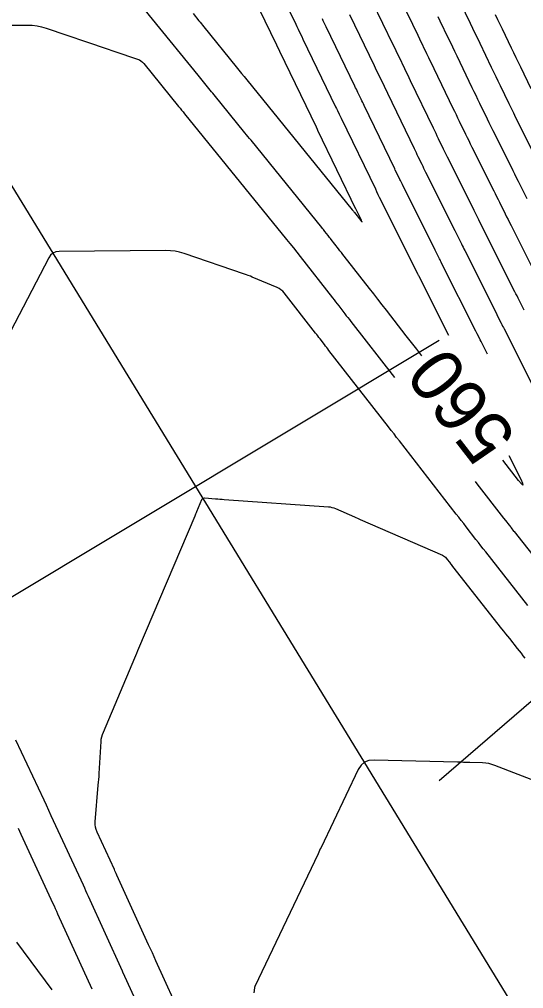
# Model space of a CAD drawing. Extents: x 954385 to 988206, y 1868364 to 1924553.
# Drawn here: x 957159.4 to 957216.7, y 1920795.3 to 1920905.5 of the extents above; entities that cross this region are included whole.
import ezdxf

# ---------------------------------------------------------------- set-up
doc = ezdxf.new("R2010")
doc.units = 0
for name, color, linetype in [('Default', 7, 'Continuous'), ('Ex_Contour Labels', 7, 'Continuous'), ('Ex_Major Contours', 7, 'Continuous'), ('Ex_Minor Contours', 7, 'Continuous'), ('Slopes', 7, 'Continuous')]:
    doc.layers.add(name, color=color, linetype=linetype)

msp = doc.modelspace()

# ---------------------------------------------------------------- linework, layer by layer
at = {"layer": 'Default'}
msp.add_line((957221.14, 1920784.24), (956045.8, 1922705.18), dxfattribs=at)
at = {"layer": 'Ex_Major Contours'}
for points in [[(957187.32, 1920912.19), (957190.83, 1920904.93), (957190.97, 1920904.64), (957191.1, 1920904.36), (957191.38, 1920903.79), (957191.51, 1920903.51), (957191.65, 1920903.22), (957195.36, 1920895.53), (957195.47, 1920895.32), (957195.57, 1920895.1), (957195.78, 1920894.67), (957195.88, 1920894.46), (957195.98, 1920894.24), (957199.88, 1920886.18), (957200.02, 1920885.87), (957200.17, 1920885.56), (957200.21, 1920885.48), (957200.25, 1920885.4), (957200.29, 1920885.33), (957200.32, 1920885.25), (957204.47, 1920876.95), (957204.68, 1920876.53), (957204.71, 1920876.48), (957204.73, 1920876.43), (957204.76, 1920876.37), (957204.79, 1920876.32), (957208.19, 1920869.54)], [(957205.18, 1920867.19), (957204.58, 1920867.96), (957204.28, 1920868.34), (957203.99, 1920868.72), (957203.69, 1920869.1), (957203.4, 1920869.48), (957201.13, 1920872.41), (957200.65, 1920873.02), (957200.17, 1920873.63), (957199.69, 1920874.25), (957199.21, 1920874.86), (957196.35, 1920878.52), (957196.18, 1920878.73), (957196.02, 1920878.95), (957195.85, 1920879.16), (957195.68, 1920879.38), (957194.86, 1920880.43), (957194.77, 1920880.54), (957194.68, 1920880.66), (957194.59, 1920880.77), (957194.5, 1920880.88), (957194.15, 1920881.34), (957194.06, 1920881.45), (957193.97, 1920881.56), (957193.88, 1920881.68), (957193.79, 1920881.79), (957185.75, 1920891.71), (957185.57, 1920891.92), (957185.4, 1920892.13), (957185.23, 1920892.34), (957185.06, 1920892.55), (957181.57, 1920896.86), (957181.41, 1920897.05), (957181.26, 1920897.23), (957181.11, 1920897.42), (957180.95, 1920897.61), (957180.34, 1920898.37), (957180.19, 1920898.56), (957180.03, 1920898.75), (957179.88, 1920898.94), (957179.73, 1920899.13), (957169.36, 1920911.9)], [(957217.13, 1920885.05), (957216.34, 1920886.64), (957216.14, 1920887.04), (957215.94, 1920887.44), (957215.74, 1920887.84), (957215.54, 1920888.23), (957213.48, 1920892.35), (957213.26, 1920892.79), (957213.05, 1920893.23), (957212.83, 1920893.68), (957212.61, 1920894.12), (957211.76, 1920895.9), (957211.54, 1920896.35), (957211.33, 1920896.79), (957211.11, 1920897.23), (957210.9, 1920897.68), (957209.16, 1920901.29), (957208.92, 1920901.79), (957208.68, 1920902.28), (957208.44, 1920902.78), (957208.2, 1920903.28), (957207.24, 1920905.26), (957207, 1920905.76)], [(957215.05, 1920855.87), (957216.4, 1920853.2), (957216.62, 1920852.71), (957216.66, 1920852.52), (957216.51, 1920852.64), (957216.16, 1920853.05), (957214.38, 1920855.35)]]:
    msp.add_lwpolyline(points, dxfattribs=at)
at = {"layer": 'Ex_Minor Contours'}
for points in [[(957179.16, 1920906.12), (957179.82, 1920905.3), (957179.96, 1920905.13), (957180.1, 1920904.96), (957180.24, 1920904.79), (957180.38, 1920904.62), (957184.06, 1920900.07), (957184.37, 1920899.7), (957184.67, 1920899.32), (957184.98, 1920898.95), (957185.28, 1920898.57), (957197.25, 1920883.81), (957197.32, 1920883.73), (957197.38, 1920883.65), (957197.45, 1920883.57), (957197.51, 1920883.49), (957198.21, 1920882.59), (957198.32, 1920882.47), (957198.37, 1920882.43), (957198.36, 1920882.49), (957198.29, 1920882.64), (957197.69, 1920883.83), (957197.68, 1920883.85), (957197.67, 1920883.88), (957193.35, 1920892.83), (957193.29, 1920892.95), (957193.18, 1920893.19), (957189.01, 1920901.82), (957188.9, 1920902.06), (957188.73, 1920902.42), (957188.67, 1920902.53), (957184.68, 1920910.81)], [(957202.21, 1920908.83), (957204.1, 1920904.91), (957204.3, 1920904.49), (957204.5, 1920904.07), (957204.7, 1920903.65), (957204.91, 1920903.23), (957205.71, 1920901.56), (957205.92, 1920901.14), (957206.12, 1920900.72), (957206.32, 1920900.3), (957206.52, 1920899.88), (957208.69, 1920895.38), (957208.87, 1920895.01), (957209.05, 1920894.64), (957209.23, 1920894.27), (957209.41, 1920893.89), (957210.13, 1920892.41), (957210.31, 1920892.04), (957210.49, 1920891.67), (957210.67, 1920891.3), (957210.85, 1920890.93), (957213.33, 1920885.98), (957213.49, 1920885.65), (957213.65, 1920885.32), (957213.82, 1920884.99), (957213.98, 1920884.66), (957214.64, 1920883.35), (957214.8, 1920883.02), (957214.97, 1920882.69), (957215.13, 1920882.36), (957215.3, 1920882.03), (957217.97, 1920876.71)], [(957216.8, 1920872.39), (957216.68, 1920872.62), (957216.21, 1920873.55), (957216.1, 1920873.78), (957215.98, 1920874.01), (957215.86, 1920874.24), (957215.75, 1920874.48), (957212.67, 1920880.6), (957212.54, 1920880.86), (957212.41, 1920881.12), (957212.28, 1920881.38), (957212.15, 1920881.64), (957211.63, 1920882.68), (957211.37, 1920883.2), (957211.11, 1920883.72), (957208.22, 1920889.51), (957208.07, 1920889.81), (957207.93, 1920890.1), (957207.78, 1920890.4), (957207.64, 1920890.7), (957207.06, 1920891.89), (957206.92, 1920892.19), (957206.78, 1920892.48), (957206.63, 1920892.78), (957206.49, 1920893.08), (957203.89, 1920898.47), (957203.72, 1920898.81), (957203.56, 1920899.15), (957203.39, 1920899.49), (957203.23, 1920899.84), (957202.57, 1920901.2), (957202.41, 1920901.54), (957202.24, 1920901.88), (957202.08, 1920902.22), (957201.91, 1920902.56), (957199.57, 1920907.43)], [(957217.75, 1920890.49), (957216.12, 1920893.77), (957215.86, 1920894.28), (957215.61, 1920894.8), (957215.35, 1920895.32), (957215.1, 1920895.84), (957214.1, 1920897.91), (957213.85, 1920898.43), (957213.6, 1920898.94), (957213.35, 1920899.46), (957213.1, 1920899.98), (957211.79, 1920902.7), (957211.51, 1920903.28), (957211.24, 1920903.85), (957210.96, 1920904.42), (957210.68, 1920905), (957209.56, 1920907.33)], [(957212.61, 1920867.41), (957211.89, 1920868.82), (957211.79, 1920869.02), (957211.7, 1920869.22), (957211.45, 1920869.72), (957211.3, 1920870.01), (957207.41, 1920877.75), (957207.35, 1920877.87), (957207.29, 1920877.99), (957207.23, 1920878.11), (957207.17, 1920878.23), (957206.87, 1920878.84), (957206.68, 1920879.21), (957202.96, 1920886.67), (957202.88, 1920886.82), (957202.81, 1920886.97), (957202.73, 1920887.12), (957202.66, 1920887.27), (957202.3, 1920888.03), (957202.15, 1920888.33), (957202.08, 1920888.48), (957198.62, 1920895.65), (957198.53, 1920895.84), (957198.44, 1920896.02), (957198.35, 1920896.21), (957198.26, 1920896.39), (957197.9, 1920897.13), (957197.81, 1920897.32), (957197.72, 1920897.51), (957197.63, 1920897.69), (957197.55, 1920897.88), (957194.29, 1920904.62), (957194.18, 1920904.85), (957194.07, 1920905.07), (957193.96, 1920905.3), (957193.86, 1920905.52)], [(957196.93, 1920906.02), (957199.73, 1920900.22), (957199.86, 1920899.96), (957199.98, 1920899.69), (957200.11, 1920899.43), (957200.24, 1920899.17), (957200.75, 1920898.11), (957200.87, 1920897.85), (957201, 1920897.59), (957201.13, 1920897.32), (957201.25, 1920897.06), (957204.28, 1920890.78), (957204.39, 1920890.55), (957204.5, 1920890.33), (957204.61, 1920890.11), (957204.72, 1920889.88), (957205.15, 1920888.98), (957205.26, 1920888.76), (957205.37, 1920888.54), (957205.48, 1920888.31), (957205.59, 1920888.09), (957208.9, 1920881.47), (957209.09, 1920881.08), (957209.28, 1920880.7), (957209.66, 1920879.94), (957209.76, 1920879.75), (957209.85, 1920879.56), (957209.95, 1920879.37), (957210.04, 1920879.18), (957213.52, 1920872.24), (957213.69, 1920871.91), (957213.85, 1920871.58), (957214.19, 1920870.92), (957214.27, 1920870.75), (957214.35, 1920870.59), (957214.44, 1920870.42), (957214.52, 1920870.26), (957218.14, 1920863.04)], [(957217.59, 1920897.55), (957216.4, 1920900.02), (957216.14, 1920900.56), (957215.88, 1920901.1), (957215.62, 1920901.64), (957215.36, 1920902.18), (957214.32, 1920904.34), (957214.05, 1920904.88), (957213.79, 1920905.42), (957213.53, 1920905.96)], [(957156.79, 1920904.78), (957160.34, 1920904.81), (957160.88, 1920904.79), (957161.42, 1920904.73), (957161.94, 1920904.62), (957162.46, 1920904.47), (957169.39, 1920902.11), (957169.61, 1920902.04), (957169.83, 1920901.96), (957170.05, 1920901.89), (957170.27, 1920901.81), (957172.85, 1920900.93), (957173.06, 1920900.85), (957173.24, 1920900.74), (957173.41, 1920900.6), (957173.56, 1920900.44), (957177.51, 1920895.56), (957177.68, 1920895.35), (957177.85, 1920895.15), (957178.02, 1920894.94), (957178.19, 1920894.73), (957189.78, 1920880.44), (957190.17, 1920879.96), (957190.56, 1920879.47), (957190.94, 1920878.99), (957191.32, 1920878.5), (957195.01, 1920873.79), (957195.18, 1920873.56), (957195.36, 1920873.34), (957195.53, 1920873.11), (957195.71, 1920872.89), (957196.41, 1920871.99), (957196.58, 1920871.77), (957196.76, 1920871.55), (957196.93, 1920871.32), (957197.11, 1920871.1), (957202.04, 1920864.75)], [(957217.2, 1920838.83), (957212.43, 1920844.91), (957212.15, 1920845.26), (957211.87, 1920845.62), (957211.59, 1920845.98), (957211.31, 1920846.34), (957210.19, 1920847.77), (957209.92, 1920848.13), (957209.64, 1920848.49), (957209.36, 1920848.85), (957209.08, 1920849.21), (957202.61, 1920857.53), (957202.3, 1920857.93), (957202, 1920858.33), (957201.69, 1920858.72), (957201.38, 1920859.12), (957194.61, 1920867.83), (957194.49, 1920867.99), (957194.36, 1920868.16), (957194.23, 1920868.32), (957194.11, 1920868.48), (957193.6, 1920869.13), (957193.47, 1920869.3), (957193.35, 1920869.46), (957193.22, 1920869.62), (957193.09, 1920869.78), (957189.52, 1920874.35), (957189.35, 1920874.55), (957189.15, 1920874.72), (957188.94, 1920874.86), (957188.7, 1920874.98), (957185.89, 1920876.16), (957185.67, 1920876.25), (957185.44, 1920876.34), (957185.22, 1920876.42), (957184.99, 1920876.5), (957178.14, 1920878.83), (957177.63, 1920878.98), (957177.11, 1920879.09), (957176.58, 1920879.15), (957176.04, 1920879.17), (957163.93, 1920879.07), (957163.55, 1920879.02), (957163.23, 1920878.88), (957162.96, 1920878.66), (957162.75, 1920878.35), (957150.64, 1920855.12)], [(957211.24, 1920852.91), (957211.43, 1920852.66), (957214.46, 1920848.76), (957214.66, 1920848.5), (957215.08, 1920847.96), (957215.16, 1920847.86), (957215.24, 1920847.76), (957215.26, 1920847.73), (957215.28, 1920847.71), (957215.3, 1920847.68), (957215.32, 1920847.66), (957215.6, 1920847.29), (957215.64, 1920847.24), (957220.72, 1920840.78)], [(957178.07, 1920791.54), (957174.94, 1920798.42), (957174.73, 1920798.87), (957174.53, 1920799.33), (957174.32, 1920799.78), (957174.11, 1920800.23), (957170.5, 1920808.18), (957170.43, 1920808.34), (957170.36, 1920808.5), (957170.28, 1920808.66), (957170.21, 1920808.81), (957168.25, 1920813.06), (957168.14, 1920813.34), (957168.07, 1920813.63), (957168.04, 1920813.93), (957168.05, 1920814.23), (957168.39, 1920818.4), (957168.42, 1920818.73), (957168.44, 1920819.05), (957168.47, 1920819.38), (957168.49, 1920819.71), (957168.71, 1920823.34), (957168.73, 1920823.61), (957168.78, 1920823.89), (957168.86, 1920824.15), (957168.96, 1920824.41), (957172.53, 1920832.87), (957172.65, 1920833.14), (957172.76, 1920833.42), (957172.88, 1920833.69), (957172.99, 1920833.97), (957179.38, 1920849.01), (957179.43, 1920849.13), (957179.48, 1920849.25), (957179.54, 1920849.38), (957179.59, 1920849.5), (957180.16, 1920850.86), (957180.21, 1920850.95), (957180.29, 1920851.01), (957180.37, 1920851.04), (957180.48, 1920851.05), (957181.72, 1920850.96), (957181.97, 1920850.94), (957182.21, 1920850.92), (957182.46, 1920850.91), (957182.7, 1920850.89), (957194.54, 1920850.05), (957194.75, 1920850.02), (957194.95, 1920849.98), (957195.15, 1920849.92), (957195.35, 1920849.85), (957197.5, 1920848.91), (957197.67, 1920848.83), (957197.84, 1920848.76), (957198.01, 1920848.69), (957198.17, 1920848.61), (957207.51, 1920844.53), (957207.63, 1920844.46), (957207.75, 1920844.39), (957207.85, 1920844.3), (957207.94, 1920844.19), (957208.41, 1920843.58), (957208.43, 1920843.56), (957208.45, 1920843.53), (957208.47, 1920843.51), (957208.49, 1920843.48), (957208.66, 1920843.27), (957214.23, 1920836.17), (957214.45, 1920835.89), (957214.67, 1920835.61), (957214.89, 1920835.34), (957215.11, 1920835.06), (957216, 1920833.95), (957216.22, 1920833.67), (957216.44, 1920833.39), (957216.66, 1920833.11), (957216.88, 1920832.83)], [(957158.98, 1920823.56), (957162.18, 1920816.73), (957162.45, 1920816.14), (957162.72, 1920815.55), (957163, 1920814.96), (957163.27, 1920814.38), (957166.65, 1920807.05), (957166.8, 1920806.73), (957166.94, 1920806.41), (957167.09, 1920806.09), (957167.24, 1920805.77), (957171.09, 1920797.29), (957171.14, 1920797.18), (957171.59, 1920796.19), (957175.06, 1920788.56)], [(957222.42, 1920817.19), (957213.45, 1920820.64), (957213.11, 1920820.76), (957212.77, 1920820.84), (957212.42, 1920820.89), (957212.06, 1920820.92), (957210.63, 1920820.96), (957210.27, 1920820.97), (957209.91, 1920820.98), (957209.56, 1920820.99), (957209.2, 1920821), (957199.73, 1920821.25), (957199.14, 1920821.2), (957198.65, 1920821), (957198.25, 1920820.65), (957197.93, 1920820.16), (957193.71, 1920811.32), (957193.62, 1920811.14), (957193.54, 1920810.96), (957193.45, 1920810.78), (957193.36, 1920810.6), (957186.19, 1920795.52), (957186.17, 1920795.48), (957186.16, 1920795.44), (957186.15, 1920795.4), (957186.14, 1920795.36), (957186.08, 1920794.77)], [(957167.68, 1920795.2), (957163.8, 1920803.73), (957163.67, 1920804.03), (957163.53, 1920804.32), (957163.4, 1920804.62), (957163.26, 1920804.91), (957159.62, 1920812.8), (957159.47, 1920813.13), (957159.31, 1920813.46)], [(957159.08, 1920800.54), (957163.12, 1920795.14)]]:
    msp.add_lwpolyline(points, dxfattribs=at)
at = {"layer": 'Slopes'}
for points in [[(957207.13, 1920868.93), (957087.13, 1920796.9), (957090.04, 1920802.14), (957087.13, 1920796.9), (957093.13, 1920797)], [(957207.13, 1920818.93), (957244.79, 1920851.42), (957242.81, 1920845.76), (957244.79, 1920851.42), (957238.89, 1920850.3)]]:
    msp.add_lwpolyline(points, dxfattribs=at)

# ---------------------------------------------------------------- texts
at = {"layer": 'Ex_Contour Labels'}
msp.add_text('560', height=6, rotation=127.8394, dxfattribs=at).set_placement((957216.09, 1920858.03))

doc.saveas('drawing.dxf')
